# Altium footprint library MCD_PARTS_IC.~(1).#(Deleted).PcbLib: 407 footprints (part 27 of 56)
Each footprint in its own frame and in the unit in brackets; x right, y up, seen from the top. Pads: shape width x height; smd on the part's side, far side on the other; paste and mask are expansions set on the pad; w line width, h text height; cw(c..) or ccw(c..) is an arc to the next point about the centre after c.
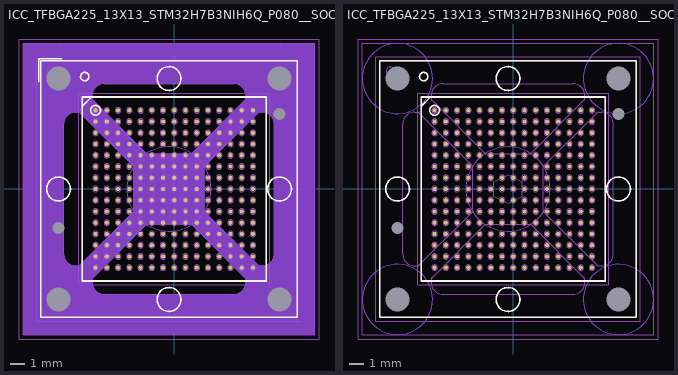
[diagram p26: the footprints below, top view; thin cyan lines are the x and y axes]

## ICC_TFBGA225_13X13_STM32H7B3NIH6Q_P080__SOCKET_IRONWOOD_CS1222291MF_REV-A [mm] "MCD-00670"
height 8.25
pads (231):
  round 0.3 smd mask+0.05: A1(-5.6,5.6) A2(-4.8,5.6) A3(-4,5.6) A4(-3.2,5.6) A5(-2.4,5.6) A6(-1.6,5.6) A7(-0.8,5.6) A8(0,5.6) A9(0.8,5.6) A10(1.6,5.6) A11(2.4,5.6) A12(3.2,5.6) A13(4,5.6) A14(4.8,5.6) A15(5.6,5.6) B1(-5.6,4.8) B2(-4.8,4.8) B3(-4,4.8) B4(-3.2,4.8) B5(-2.4,4.8) B6(-1.6,4.8) B7(-0.8,4.8) B8(0,4.8) B9(0.8,4.8) B10(1.6,4.8) B11(2.4,4.8) B12(3.2,4.8) B13(4,4.8) B14(4.8,4.8) B15(5.6,4.8) C1(-5.6,4) C2(-4.8,4) C3(-4,4) C4(-3.2,4) C5(-2.4,4) C6(-1.6,4) C7(-0.8,4) C8(0,4) C9(0.8,4) C10(1.6,4) C11(2.4,4) C12(3.2,4) C13(4,4) C14(4.8,4) C15(5.6,4) D1(-5.6,3.2) D2(-4.8,3.2) D3(-4,3.2) D4(-3.2,3.2) D5(-2.4,3.2) D6(-1.6,3.2) D7(-0.8,3.2) D8(0,3.2) D9(0.8,3.2) D10(1.6,3.2) D11(2.4,3.2) D12(3.2,3.2) D13(4,3.2) D14(4.8,3.2) D15(5.6,3.2) E1(-5.6,2.4) E2(-4.8,2.4) E3(-4,2.4) E4(-3.2,2.4) E5(-2.4,2.4) E6(-1.6,2.4) E7(-0.8,2.4) E8(0,2.4) E9(0.8,2.4) E10(1.6,2.4) E11(2.4,2.4) E12(3.2,2.4) E13(4,2.4) E14(4.8,2.4) E15(5.6,2.4) F1(-5.6,1.6) F2(-4.8,1.6) F3(-4,1.6) F4(-3.2,1.6) F5(-2.4,1.6) F6(-1.6,1.6) F7(-0.8,1.6) F8(0,1.6) F9(0.8,1.6) F10(1.6,1.6) F11(2.4,1.6) F12(3.2,1.6) F13(4,1.6) F14(4.8,1.6) F15(5.6,1.6) G1(-5.6,0.8) G2(-4.8,0.8) G3(-4,0.8) G4(-3.2,0.8) G5(-2.4,0.8) G6(-1.6,0.8) G7(-0.8,0.8) G8(0,0.8) G9(0.8,0.8) G10(1.6,0.8) G11(2.4,0.8) G12(3.2,0.8) G13(4,0.8) G14(4.8,0.8) G15(5.6,0.8) H1(-5.6,0) H2(-4.8,0) H3(-4,0) H4(-3.2,0) H5(-2.4,0) H6(-1.6,0) H7(-0.8,0) H8(0,0) H9(0.8,0) H10(1.6,0) H11(2.4,0) H12(3.2,0) H13(4,0) H14(4.8,0) H15(5.6,0) J1(-5.6,-0.8) J2(-4.8,-0.8) J3(-4,-0.8) J4(-3.2,-0.8) J5(-2.4,-0.8) J6(-1.6,-0.8) J7(-0.8,-0.8) J8(0,-0.8) J9(0.8,-0.8) J10(1.6,-0.8) J11(2.4,-0.8) J12(3.2,-0.8) J13(4,-0.8) J14(4.8,-0.8) J15(5.6,-0.8) K1(-5.6,-1.6) K2(-4.8,-1.6) K3(-4,-1.6) K4(-3.2,-1.6) K5(-2.4,-1.6) K6(-1.6,-1.6) K7(-0.8,-1.6) K8(0,-1.6) K9(0.8,-1.6) K10(1.6,-1.6) K11(2.4,-1.6) K12(3.2,-1.6) K13(4,-1.6) K14(4.8,-1.6) K15(5.6,-1.6) L1(-5.6,-2.4) L2(-4.8,-2.4) L3(-4,-2.4) L4(-3.2,-2.4) L5(-2.4,-2.4) L6(-1.6,-2.4) L7(-0.8,-2.4) L8(0,-2.4) L9(0.8,-2.4) L10(1.6,-2.4) L11(2.4,-2.4) L12(3.2,-2.4) L13(4,-2.4) L14(4.8,-2.4) L15(5.6,-2.4) M1(-5.6,-3.2) M2(-4.8,-3.2) M3(-4,-3.2) M4(-3.2,-3.2) M5(-2.4,-3.2) M6(-1.6,-3.2) M7(-0.8,-3.2) M8(0,-3.2) M9(0.8,-3.2) M10(1.6,-3.2) M11(2.4,-3.2) M12(3.2,-3.2) M13(4,-3.2) M14(4.8,-3.2) M15(5.6,-3.2) N1(-5.6,-4) N2(-4.8,-4) N3(-4,-4) N4(-3.2,-4) N5(-2.4,-4) N6(-1.6,-4) N7(-0.8,-4) N8(0,-4) N9(0.8,-4) N10(1.6,-4) N11(2.4,-4) N12(3.2,-4) N13(4,-4) N14(4.8,-4) N15(5.6,-4) P1(-5.6,-4.8) P2(-4.8,-4.8) P3(-4,-4.8) P4(-3.2,-4.8) P5(-2.4,-4.8) P6(-1.6,-4.8) P7(-0.8,-4.8) P8(0,-4.8) P9(0.8,-4.8) P10(1.6,-4.8) P11(2.4,-4.8) P12(3.2,-4.8) P13(4,-4.8) P14(4.8,-4.8) P15(5.6,-4.8) R1(-5.6,-5.6) R2(-4.8,-5.6) R3(-4,-5.6) R4(-3.2,-5.6) R5(-2.4,-5.6) R6(-1.6,-5.6) R7(-0.8,-5.6) R8(0,-5.6) R9(0.8,-5.6) R10(1.6,-5.6) R11(2.4,-5.6) R12(3.2,-5.6) R13(4,-5.6) R14(4.8,-5.6) R15(5.6,-5.6)
  round 0 hole 0.85 unplated mask+0.05: NPTH1(7.487,5.322) NPTH2(-8.238,-2.783)
  round 0 hole 1.71 unplated mask+0.05: PTH1(-8.238,7.862) PTH2(7.487,7.862) PTH3(7.487,-7.863) PTH4(-8.238,-7.863)
Bottom Layer keep-out:
  circle w0.01: c7.487,-7.863 r2.5
  circle w0.01: c-8.238,-7.863 r2.5
  circle w0.01: c-8.238,7.862 r2.5
  circle w0.01: c7.487,7.862 r2.5
  region: -0.376,0 -0.376,2.5 -1.976,2.5 -5.776,6.3 -5.792,6.317 -5.818,6.356 -5.836,6.4 -5.845,6.446 -5.846,6.469 -5.846,6.63 -5.842,6.715 -5.809,6.883 -5.743,7.04 -5.649,7.182 -5.528,7.303 -5.386,7.397 -5.229,7.463 -5.061,7.496 -4.976,7.5 -0.376,7.5 -0.376,10.365 -10.74,10.365 -10.74,-10.365 -0.376,-10.365 -0.376,-7.5 -4.976,-7.5 -5.061,-7.496 -5.229,-7.463 -5.386,-7.397 -5.528,-7.303 -5.649,-7.182 -5.743,-7.04 -5.809,-6.883 -5.842,-6.715 -5.846,-6.63 -5.846,-6.469 -5.845,-6.446 -5.836,-6.4 -5.818,-6.356 -5.792,-6.317 -5.776,-6.3 -1.976,-2.5 -0.376,-2.5 -0.376,0 -2.876,0 -2.876,-1.6 -6.676,-5.4 -6.693,-5.416 -6.732,-5.442 -6.776,-5.46 -6.822,-5.469 -6.845,-5.47 -7.006,-5.47 -7.091,-5.466 -7.259,-5.433 -7.416,-5.367 -7.558,-5.273 -7.679,-5.152 -7.773,-5.01 -7.839,-4.853 -7.872,-4.685 -7.876,-4.6 -7.876,4.6 -7.872,4.685 -7.839,4.853 -7.773,5.01 -7.679,5.152 -7.558,5.273 -7.416,5.367 -7.259,5.433 -7.091,5.466 -7.006,5.47 -6.845,5.47 -6.822,5.469 -6.776,5.46 -6.732,5.442 -6.693,5.416 -6.676,5.4 -2.876,1.6 -2.876,0
  region: -0.376,0 -0.376,-2.5 1.224,-2.5 5.024,-6.3 5.04,-6.317 5.066,-6.356 5.084,-6.4 5.093,-6.446 5.094,-6.469 5.094,-6.63 5.09,-6.715 5.057,-6.883 4.991,-7.04 4.897,-7.182 4.776,-7.303 4.634,-7.397 4.477,-7.463 4.309,-7.496 4.224,-7.5 -0.376,-7.5 -0.376,-10.365 9.988,-10.365 9.988,10.365 -0.376,10.365 -0.376,7.5 4.224,7.5 4.309,7.496 4.477,7.463 4.634,7.397 4.776,7.303 4.897,7.182 4.991,7.04 5.057,6.883 5.09,6.715 5.094,6.63 5.094,6.469 5.093,6.446 5.084,6.4 5.066,6.356 5.04,6.317 5.024,6.3 1.224,2.5 -0.376,2.5 -0.376,0 2.124,0 2.124,1.6 5.924,5.4 5.941,5.416 5.98,5.442 6.024,5.46 6.07,5.469 6.093,5.47 6.254,5.47 6.339,5.466 6.507,5.433 6.664,5.367 6.806,5.273 6.927,5.152 7.021,5.01 7.087,4.853 7.12,4.685 7.124,4.6 7.124,-4.6 7.12,-4.685 7.087,-4.853 7.021,-5.01 6.927,-5.152 6.806,-5.273 6.664,-5.367 6.507,-5.433 6.339,-5.466 6.254,-5.47 6.093,-5.47 6.07,-5.469 6.024,-5.46 5.98,-5.442 5.941,-5.416 5.924,-5.4 2.124,-1.6 2.124,0
Top Overlay:
  circle w0.12: c-5.6,5.6 r0.35
  circle w0.12: c-8.238,0 r0.85
  circle w0.12: c-0.375,7.862 r0.85
  circle w0.12: c7.487,0 r0.85
  circle w0.12: c-0.375,-7.863 r0.85
  circle w0.12: c-6.375,8 r0.3
  lines w0.12: -9.65,7.625 -9.65,9.275 -8,9.275 ; -6.55,5.895 -5.895,6.55 ; -9.5,-9.125 -9.5,9.125 8.75,9.125 8.75,-9.125 -9.5,-9.125 ; -6.55,-6.55 6.55,-6.55 6.55,6.55 -6.55,6.55 -6.55,-6.55
Bottom Overlay:
  lines w0.12: -10.75,-10.375 -10.75,10.375 -7.625,10.375 10,10.375 10,-10.375 -10.75,-10.375
M14-Top Assembly:
  drawing of 245 lines, arcs and shapes, not listed
  text "'.Designator'" at -6.5,7.25 h0.75
  text "A1" at -5.85,5.425 h0.4
M15-Bottom Assembly:
  lines w0.01: -2.891,1.615 -2.891,1.615 ; -2.891,1.615 -6.676,5.4 ccw(c-6.845,5.231) -6.845,5.47 -7.006,5.47 ccw(c-7.006,4.6) -7.876,4.6 -7.876,-4.6 ccw(c-7.006,-4.6) -7.006,-5.47 -6.845,-5.47 ccw(c-6.845,-5.231) -6.676,-5.4 -2.891,-1.615 -2.876,-1.6 -2.876,1.6 ; -2.891,1.615 -2.876,1.6 ; -2.876,1.6 -2.876,1.6 ; -1.991,-2.515 -1.976,-2.5 ; -1.991,-2.515 -5.776,-6.3 ccw(c-5.607,-6.469) -5.846,-6.469 -5.846,-6.63 ccw(c-4.976,-6.63) -4.976,-7.5 4.224,-7.5 ccw(c4.224,-6.63) 5.094,-6.63 5.094,-6.469 ccw(c4.855,-6.469) 5.024,-6.3 1.239,-2.515 1.224,-2.5 -1.976,-2.5 ; -1.991,-2.515 -1.991,-2.515 ; -1.976,-2.5 -1.976,-2.5 ; 1.224,2.5 -1.976,2.5 -1.991,2.515 -5.776,6.3 cw(c-5.607,6.469) -5.846,6.469 -5.846,6.63 cw(c-4.976,6.63) -4.976,7.5 4.224,7.5 cw(c4.224,6.63) 5.094,6.63 5.094,6.469 cw(c4.855,6.469) 5.024,6.3 1.239,2.515 ; 1.224,2.5 1.224,2.5 ; 1.224,2.5 1.239,2.515 ; 1.239,2.515 1.239,2.515 ; 2.124,-1.6 2.124,1.6 2.139,1.615 5.924,5.4 cw(c6.093,5.231) 6.093,5.47 6.254,5.47 cw(c6.254,4.6) 7.124,4.6 7.124,-4.6 cw(c6.254,-4.6) 6.254,-5.47 6.093,-5.47 cw(c6.093,-5.231) 5.924,-5.4 2.139,-1.615 ; 2.124,-1.6 2.124,-1.6 ; 2.124,-1.6 2.139,-1.615 ; 2.139,-1.615 2.139,-1.615 ; -10.74,-10.365 9.99,-10.365 9.99,10.365 -10.74,10.365 -10.74,-10.365
M16-Top Courtyard:
  lines w0.01: -9.8,-9.425 9.05,-9.425 9.05,9.425 -9.8,9.425 -9.8,8.5 -9.8,-9.425 ; -6.8,-6.8 -6.8,6.8 6.8,6.8 6.8,-6.8 -6.8,-6.8
M17-Bottom Courtyard:
  lines w0.01: -11.05,-10.675 -11.05,10.675 10.3,10.675 10.3,-10.675 -11.05,-10.675
3D body: height 1.21, standoff 1.2, extent -5.898,5.301 -5.3,5.9
3D body: height 0.36, standoff -0.04, extent 5.401,-5.797 5.8,-5.403
3D body: height 0.36, standoff -0.04, extent 4.601,-5.797 5,-5.403
3D body: height 0.36, standoff -0.04, extent 3.801,-5.797 4.2,-5.403
3D body: height 0.36, standoff -0.04, extent 3.001,-5.797 3.4,-5.403
3D body: height 0.36, standoff -0.04, extent 2.201,-5.797 2.6,-5.403
3D body: height 0.36, standoff -0.04, extent -1.799,-5.797 -1.4,-5.403
3D body: height 0.36, standoff -0.04, extent -0.999,-5.797 -0.6,-5.403
3D body: height 0.36, standoff -0.04, extent -0.199,-5.797 0.2,-5.403
3D body: height 0.36, standoff -0.04, extent 0.601,-5.797 1,-5.403
3D body: height 0.36, standoff -0.04, extent 1.401,-5.797 1.8,-5.403
3D body: height 0.36, standoff -0.04, extent -5.799,-5.797 -5.4,-5.403
3D body: height 0.36, standoff -0.04, extent -4.999,-5.797 -4.6,-5.403
3D body: height 0.36, standoff -0.04, extent -4.199,-5.797 -3.8,-5.403
3D body: height 0.36, standoff -0.04, extent -3.399,-5.797 -3,-5.403
3D body: height 0.36, standoff -0.04, extent -2.599,-5.797 -2.2,-5.403
3D body: height 0.36, standoff -0.04, extent 5.401,-4.997 5.8,-4.603
3D body: height 0.36, standoff -0.04, extent 4.601,-4.997 5,-4.603
3D body: height 0.36, standoff -0.04, extent 3.801,-4.997 4.2,-4.603
3D body: height 0.36, standoff -0.04, extent 3.001,-4.997 3.4,-4.603
3D body: height 0.36, standoff -0.04, extent 2.201,-4.997 2.6,-4.603
3D body: height 0.36, standoff -0.04, extent -1.799,-4.997 -1.4,-4.603
3D body: height 0.36, standoff -0.04, extent -0.999,-4.997 -0.6,-4.603
3D body: height 0.36, standoff -0.04, extent -0.199,-4.997 0.2,-4.603
3D body: height 0.36, standoff -0.04, extent 0.601,-4.997 1,-4.603
3D body: height 0.36, standoff -0.04, extent 1.401,-4.997 1.8,-4.603
3D body: height 0.36, standoff -0.04, extent -5.799,-4.997 -5.4,-4.603
3D body: height 0.36, standoff -0.04, extent -4.999,-4.997 -4.6,-4.603
3D body: height 0.36, standoff -0.04, extent -4.199,-4.997 -3.8,-4.603
3D body: height 0.36, standoff -0.04, extent -3.399,-4.997 -3,-4.603
3D body: height 0.36, standoff -0.04, extent -2.599,-4.997 -2.2,-4.603
3D body: height 0.36, standoff -0.04, extent 5.401,-4.197 5.8,-3.803
3D body: height 0.36, standoff -0.04, extent 4.601,-4.197 5,-3.803
3D body: height 0.36, standoff -0.04, extent 3.801,-4.197 4.2,-3.803
3D body: height 0.36, standoff -0.04, extent 3.001,-4.197 3.4,-3.803
3D body: height 0.36, standoff -0.04, extent 2.201,-4.197 2.6,-3.803
3D body: height 0.36, standoff -0.04, extent -1.799,-4.197 -1.4,-3.803
3D body: height 0.36, standoff -0.04, extent -0.999,-4.197 -0.6,-3.803
3D body: height 0.36, standoff -0.04, extent -0.199,-4.197 0.2,-3.803
3D body: height 0.36, standoff -0.04, extent 0.601,-4.197 1,-3.803
3D body: height 0.36, standoff -0.04, extent 1.401,-4.197 1.8,-3.803
3D body: height 0.36, standoff -0.04, extent -5.799,-4.197 -5.4,-3.803
3D body: height 0.36, standoff -0.04, extent -4.999,-4.197 -4.6,-3.803
3D body: height 0.36, standoff -0.04, extent -4.199,-4.197 -3.8,-3.803
3D body: height 0.36, standoff -0.04, extent -3.399,-4.197 -3,-3.803
3D body: height 0.36, standoff -0.04, extent -2.599,-4.197 -2.2,-3.803
3D body: height 0.36, standoff -0.04, extent 5.401,-3.397 5.8,-3.003
3D body: height 0.36, standoff -0.04, extent 4.601,-3.397 5,-3.003
3D body: height 0.36, standoff -0.04, extent 3.801,-3.397 4.2,-3.003
3D body: height 0.36, standoff -0.04, extent 3.001,-3.397 3.4,-3.003
3D body: height 0.36, standoff -0.04, extent 2.201,-3.397 2.6,-3.003
3D body: height 0.36, standoff -0.04, extent -1.799,-3.397 -1.4,-3.003
3D body: height 0.36, standoff -0.04, extent -0.999,-3.397 -0.6,-3.003
3D body: height 0.36, standoff -0.04, extent -0.199,-3.397 0.2,-3.003
3D body: height 0.36, standoff -0.04, extent 0.601,-3.397 1,-3.003
3D body: height 0.36, standoff -0.04, extent 1.401,-3.397 1.8,-3.003
3D body: height 0.36, standoff -0.04, extent -5.799,-3.397 -5.4,-3.003
3D body: height 0.36, standoff -0.04, extent -4.999,-3.397 -4.6,-3.003
3D body: height 0.36, standoff -0.04, extent -4.199,-3.397 -3.8,-3.003
3D body: height 0.36, standoff -0.04, extent -3.399,-3.397 -3,-3.003
3D body: height 0.36, standoff -0.04, extent -2.599,-3.397 -2.2,-3.003
3D body: height 0.36, standoff -0.04, extent 5.401,-2.597 5.8,-2.203
3D body: height 0.36, standoff -0.04, extent 4.601,-2.597 5,-2.203
3D body: height 0.36, standoff -0.04, extent 3.801,-2.597 4.2,-2.203
3D body: height 0.36, standoff -0.04, extent 3.001,-2.597 3.4,-2.203
3D body: height 0.36, standoff -0.04, extent 2.201,-2.597 2.6,-2.203
3D body: height 0.36, standoff -0.04, extent -1.799,-2.597 -1.4,-2.203
3D body: height 0.36, standoff -0.04, extent -0.999,-2.597 -0.6,-2.203
3D body: height 0.36, standoff -0.04, extent -0.199,-2.597 0.2,-2.203
3D body: height 0.36, standoff -0.04, extent 0.601,-2.597 1,-2.203
3D body: height 0.36, standoff -0.04, extent 1.401,-2.597 1.8,-2.203
3D body: height 0.36, standoff -0.04, extent -5.799,-2.597 -5.4,-2.203
3D body: height 0.36, standoff -0.04, extent -4.999,-2.597 -4.6,-2.203
3D body: height 0.36, standoff -0.04, extent -4.199,-2.597 -3.8,-2.203
3D body: height 0.36, standoff -0.04, extent -3.399,-2.597 -3,-2.203
3D body: height 0.36, standoff -0.04, extent -2.599,-2.597 -2.2,-2.203
3D body: height 0.36, standoff -0.04, extent 5.401,-1.797 5.8,-1.403
3D body: height 0.36, standoff -0.04, extent 4.601,-1.797 5,-1.403
3D body: height 0.36, standoff -0.04, extent 3.801,-1.797 4.2,-1.403
3D body: height 0.36, standoff -0.04, extent 3.001,-1.797 3.4,-1.403
3D body: height 0.36, standoff -0.04, extent 2.201,-1.797 2.6,-1.403
3D body: height 0.36, standoff -0.04, extent -1.799,-1.797 -1.4,-1.403
3D body: height 0.36, standoff -0.04, extent -0.999,-1.797 -0.6,-1.403
3D body: height 0.36, standoff -0.04, extent -0.199,-1.797 0.2,-1.403
3D body: height 0.36, standoff -0.04, extent 0.601,-1.797 1,-1.403
3D body: height 0.36, standoff -0.04, extent 1.401,-1.797 1.8,-1.403
3D body: height 0.36, standoff -0.04, extent -5.799,-1.797 -5.4,-1.403
3D body: height 0.36, standoff -0.04, extent -4.999,-1.797 -4.6,-1.403
3D body: height 0.36, standoff -0.04, extent -4.199,-1.797 -3.8,-1.403
3D body: height 0.36, standoff -0.04, extent -3.399,-1.797 -3,-1.403
3D body: height 0.36, standoff -0.04, extent -2.599,-1.797 -2.2,-1.403
3D body: height 0.36, standoff -0.04, extent 5.401,-0.997 5.8,-0.603
3D body: height 0.36, standoff -0.04, extent 4.601,-0.997 5,-0.603
3D body: height 0.36, standoff -0.04, extent 3.801,-0.997 4.2,-0.603
3D body: height 0.36, standoff -0.04, extent 3.001,-0.997 3.4,-0.603
3D body: height 0.36, standoff -0.04, extent 2.201,-0.997 2.6,-0.603
3D body: height 0.36, standoff -0.04, extent -1.799,-0.997 -1.4,-0.603
3D body: height 0.36, standoff -0.04, extent -0.999,-0.997 -0.6,-0.603
3D body: height 0.36, standoff -0.04, extent -0.199,-0.997 0.2,-0.603
3D body: height 0.36, standoff -0.04, extent 0.601,-0.997 1,-0.603
3D body: height 0.36, standoff -0.04, extent 1.401,-0.997 1.8,-0.603
3D body: height 0.36, standoff -0.04, extent -5.799,-0.997 -5.4,-0.603
3D body: height 0.36, standoff -0.04, extent -4.999,-0.997 -4.6,-0.603
3D body: height 0.36, standoff -0.04, extent -4.199,-0.997 -3.8,-0.603
3D body: height 0.36, standoff -0.04, extent -3.399,-0.997 -3,-0.603
3D body: height 0.36, standoff -0.04, extent -2.599,-0.997 -2.2,-0.603
3D body: height 0.36, standoff -0.04, extent 5.401,-0.197 5.8,0.197
3D body: height 0.36, standoff -0.04, extent 4.601,-0.197 5,0.197
3D body: height 0.36, standoff -0.04, extent 3.801,-0.197 4.2,0.197
3D body: height 0.36, standoff -0.04, extent 3.001,-0.197 3.4,0.197
3D body: height 0.36, standoff -0.04, extent 2.201,-0.197 2.6,0.197
3D body: height 0.36, standoff -0.04, extent -1.799,-0.197 -1.4,0.197
3D body: height 0.36, standoff -0.04, extent -0.999,-0.197 -0.6,0.197
3D body: height 0.36, standoff -0.04, extent -0.199,-0.197 0.2,0.197
3D body: height 0.36, standoff -0.04, extent 0.601,-0.197 1,0.197
3D body: height 0.36, standoff -0.04, extent 1.401,-0.197 1.8,0.197
3D body: height 0.36, standoff -0.04, extent -5.799,-0.197 -5.4,0.197
3D body: height 0.36, standoff -0.04, extent -4.999,-0.197 -4.6,0.197
3D body: height 0.36, standoff -0.04, extent -4.199,-0.197 -3.8,0.197
3D body: height 0.36, standoff -0.04, extent -3.399,-0.197 -3,0.197
3D body: height 0.36, standoff -0.04, extent -2.599,-0.197 -2.2,0.197
3D body: height 0.36, standoff -0.04, extent 5.401,0.603 5.8,0.997
3D body: height 0.36, standoff -0.04, extent 4.601,0.603 5,0.997
3D body: height 0.36, standoff -0.04, extent 3.801,0.603 4.2,0.997
3D body: height 0.36, standoff -0.04, extent 3.001,0.603 3.4,0.997
3D body: height 0.36, standoff -0.04, extent 2.201,0.603 2.6,0.997
3D body: height 0.36, standoff -0.04, extent -1.799,0.603 -1.4,0.997
3D body: height 0.36, standoff -0.04, extent -0.999,0.603 -0.6,0.997
3D body: height 0.36, standoff -0.04, extent -0.199,0.603 0.2,0.997
3D body: height 0.36, standoff -0.04, extent 0.601,0.603 1,0.997
3D body: height 0.36, standoff -0.04, extent 1.401,0.603 1.8,0.997
3D body: height 0.36, standoff -0.04, extent -5.799,0.603 -5.4,0.997
3D body: height 0.36, standoff -0.04, extent -4.999,0.603 -4.6,0.997
3D body: height 0.36, standoff -0.04, extent -4.199,0.603 -3.8,0.997
3D body: height 0.36, standoff -0.04, extent -3.399,0.603 -3,0.997
3D body: height 0.36, standoff -0.04, extent -2.599,0.603 -2.2,0.997
3D body: height 0.36, standoff -0.04, extent 5.401,1.403 5.8,1.797
3D body: height 0.36, standoff -0.04, extent 4.601,1.403 5,1.797
3D body: height 0.36, standoff -0.04, extent 3.801,1.403 4.2,1.797
3D body: height 0.36, standoff -0.04, extent 3.001,1.403 3.4,1.797
3D body: height 0.36, standoff -0.04, extent 2.201,1.403 2.6,1.797
3D body: height 0.36, standoff -0.04, extent -1.799,1.403 -1.4,1.797
3D body: height 0.36, standoff -0.04, extent -0.999,1.403 -0.6,1.797
3D body: height 0.36, standoff -0.04, extent -0.199,1.403 0.2,1.797
3D body: height 0.36, standoff -0.04, extent 0.601,1.403 1,1.797
3D body: height 0.36, standoff -0.04, extent 1.401,1.403 1.8,1.797
3D body: height 0.36, standoff -0.04, extent -5.799,1.403 -5.4,1.797
3D body: height 0.36, standoff -0.04, extent -4.999,1.403 -4.6,1.797
3D body: height 0.36, standoff -0.04, extent -4.199,1.403 -3.8,1.797
3D body: height 0.36, standoff -0.04, extent -3.399,1.403 -3,1.797
3D body: height 0.36, standoff -0.04, extent -2.599,1.403 -2.2,1.797
3D body: height 0.36, standoff -0.04, extent 5.401,2.203 5.8,2.597
3D body: height 0.36, standoff -0.04, extent 4.601,2.203 5,2.597
3D body: height 0.36, standoff -0.04, extent 3.801,2.203 4.2,2.597
3D body: height 0.36, standoff -0.04, extent 3.001,2.203 3.4,2.597
3D body: height 0.36, standoff -0.04, extent 2.201,2.203 2.6,2.597
3D body: height 0.36, standoff -0.04, extent -1.799,2.203 -1.4,2.597
3D body: height 0.36, standoff -0.04, extent -0.999,2.203 -0.6,2.597
3D body: height 0.36, standoff -0.04, extent -0.199,2.203 0.2,2.597
3D body: height 0.36, standoff -0.04, extent 0.601,2.203 1,2.597
3D body: height 0.36, standoff -0.04, extent 1.401,2.203 1.8,2.597
3D body: height 0.36, standoff -0.04, extent -5.799,2.203 -5.4,2.597
3D body: height 0.36, standoff -0.04, extent -4.999,2.203 -4.6,2.597
3D body: height 0.36, standoff -0.04, extent -4.199,2.203 -3.8,2.597
3D body: height 0.36, standoff -0.04, extent -3.399,2.203 -3,2.597
3D body: height 0.36, standoff -0.04, extent -2.599,2.203 -2.2,2.597
3D body: height 0.36, standoff -0.04, extent 5.401,3.003 5.8,3.397
3D body: height 0.36, standoff -0.04, extent 4.601,3.003 5,3.397
3D body: height 0.36, standoff -0.04, extent 3.801,3.003 4.2,3.397
3D body: height 0.36, standoff -0.04, extent 3.001,3.003 3.4,3.397
3D body: height 0.36, standoff -0.04, extent 2.201,3.003 2.6,3.397
3D body: height 0.36, standoff -0.04, extent -1.799,3.003 -1.4,3.397
3D body: height 0.36, standoff -0.04, extent -0.999,3.003 -0.6,3.397
3D body: height 0.36, standoff -0.04, extent -0.199,3.003 0.2,3.397
3D body: height 0.36, standoff -0.04, extent 0.601,3.003 1,3.397
3D body: height 0.36, standoff -0.04, extent 1.401,3.003 1.8,3.397
3D body: height 0.36, standoff -0.04, extent -5.799,3.003 -5.4,3.397
3D body: height 0.36, standoff -0.04, extent -4.999,3.003 -4.6,3.397
3D body: height 0.36, standoff -0.04, extent -4.199,3.003 -3.8,3.397
3D body: height 0.36, standoff -0.04, extent -3.399,3.003 -3,3.397
3D body: height 0.36, standoff -0.04, extent -2.599,3.003 -2.2,3.397
3D body: height 0.36, standoff -0.04, extent 5.401,3.803 5.8,4.197
3D body: height 0.36, standoff -0.04, extent 4.601,3.803 5,4.197
3D body: height 0.36, standoff -0.04, extent 3.801,3.803 4.2,4.197
3D body: height 0.36, standoff -0.04, extent 3.001,3.803 3.4,4.197
3D body: height 0.36, standoff -0.04, extent 2.201,3.803 2.6,4.197
3D body: height 0.36, standoff -0.04, extent -1.799,3.803 -1.4,4.197
3D body: height 0.36, standoff -0.04, extent -0.999,3.803 -0.6,4.197
3D body: height 0.36, standoff -0.04, extent -0.199,3.803 0.2,4.197
3D body: height 0.36, standoff -0.04, extent 0.601,3.803 1,4.197
3D body: height 0.36, standoff -0.04, extent 1.401,3.803 1.8,4.197
3D body: height 0.36, standoff -0.04, extent -5.799,3.803 -5.4,4.197
3D body: height 0.36, standoff -0.04, extent -4.999,3.803 -4.6,4.197
3D body: height 0.36, standoff -0.04, extent -4.199,3.803 -3.8,4.197
3D body: height 0.36, standoff -0.04, extent -3.399,3.803 -3,4.197
3D body: height 0.36, standoff -0.04, extent -2.599,3.803 -2.2,4.197
3D body: height 0.36, standoff -0.04, extent 5.401,4.603 5.8,4.997
3D body: height 0.36, standoff -0.04, extent 4.601,4.603 5,4.997
3D body: height 0.36, standoff -0.04, extent 3.801,4.603 4.2,4.997
3D body: height 0.36, standoff -0.04, extent 3.001,4.603 3.4,4.997
3D body: height 0.36, standoff -0.04, extent 2.201,4.603 2.6,4.997
3D body: height 0.36, standoff -0.04, extent -1.799,4.603 -1.4,4.997
3D body: height 0.36, standoff -0.04, extent -0.999,4.603 -0.6,4.997
3D body: height 0.36, standoff -0.04, extent -0.199,4.603 0.2,4.997
3D body: height 0.36, standoff -0.04, extent 0.601,4.603 1,4.997
3D body: height 0.36, standoff -0.04, extent 1.401,4.603 1.8,4.997
3D body: height 0.36, standoff -0.04, extent -5.799,4.603 -5.4,4.997
3D body: height 0.36, standoff -0.04, extent -4.999,4.603 -4.6,4.997
3D body: height 0.36, standoff -0.04, extent -4.199,4.603 -3.8,4.997
3D body: height 0.36, standoff -0.04, extent -3.399,4.603 -3,4.997
3D body: height 0.36, standoff -0.04, extent -2.599,4.603 -2.2,4.997
3D body: height 0.36, standoff -0.04, extent -2.599,5.403 -2.2,5.797
3D body: height 0.36, standoff -0.04, extent -3.399,5.403 -3,5.797
3D body: height 0.36, standoff -0.04, extent -4.199,5.403 -3.8,5.797
3D body: height 0.36, standoff -0.04, extent -4.999,5.403 -4.6,5.797
3D body: height 0.36, standoff -0.04, extent -5.799,5.403 -5.4,5.797
3D body: height 0.36, standoff -0.04, extent 1.401,5.403 1.8,5.797
3D body: height 0.36, standoff -0.04, extent 0.601,5.403 1,5.797
3D body: height 0.36, standoff -0.04, extent -0.199,5.403 0.2,5.797
3D body: height 0.36, standoff -0.04, extent -0.999,5.403 -0.6,5.797
3D body: height 0.36, standoff -0.04, extent -1.799,5.403 -1.4,5.797
3D body: height 0.36, standoff -0.04, extent 2.201,5.403 2.6,5.797
3D body: height 0.36, standoff -0.04, extent 3.001,5.403 3.4,5.797
3D body: height 0.36, standoff -0.04, extent 3.801,5.403 4.2,5.797
3D body: height 0.36, standoff -0.04, extent 4.601,5.403 5,5.797
3D body: height 1.2, standoff 0.3, extent -6.55,-6.55 6.55,6.55
3D body: height 0.36, standoff -0.04, extent 5.401,5.403 5.8,5.797
3D body: height 8.26, standoff 8.25, extent -1.375,-1 0.625,1
3D body: height 5, standoff 0, extent -9.488,-9.113 8.737,9.112
3D body: height 8.25, standoff 5, extent -3.375,-3 2.625,3
3D body: height 6, standoff 5, extent -1.218,-8.711 0.475,-7.014
3D body: height 6, standoff 5, extent 6.644,-0.848 8.338,0.848
3D body: height 6, standoff 5, extent -1.218,7.014 0.475,8.711
3D body: height 6, standoff 5, extent -9.081,-0.848 -7.387,0.848
3D body: height -1.6, standoff -3.2, extent -10.74,-10.365 9.99,10.365
3D body: height -3.2, standoff -9.55, extent -10.74,-10.365 9.99,10.365

## ICC_TFBGA225_13X13_STM32H7B3NIH6Q_P080__SOCKET_IRONWOOD_CS1222291MF_REV-A_17.0 [mm]
height 8.25
pads (231):
  round 0.3 smd mask+0.05: A1(-5.6,5.6) A2(-4.8,5.6) A3(-4,5.6) A4(-3.2,5.6) A5(-2.4,5.6) A6(-1.6,5.6) A7(-0.8,5.6) A8(0,5.6) A9(0.8,5.6) A10(1.6,5.6) A11(2.4,5.6) A12(3.2,5.6) A13(4,5.6) A14(4.8,5.6) A15(5.6,5.6) B1(-5.6,4.8) B2(-4.8,4.8) B3(-4,4.8) B4(-3.2,4.8) B5(-2.4,4.8) B6(-1.6,4.8) B7(-0.8,4.8) B8(0,4.8) B9(0.8,4.8) B10(1.6,4.8) B11(2.4,4.8) B12(3.2,4.8) B13(4,4.8) B14(4.8,4.8) B15(5.6,4.8) C1(-5.6,4) C2(-4.8,4) C3(-4,4) C4(-3.2,4) C5(-2.4,4) C6(-1.6,4) C7(-0.8,4) C8(0,4) C9(0.8,4) C10(1.6,4) C11(2.4,4) C12(3.2,4) C13(4,4) C14(4.8,4) C15(5.6,4) D1(-5.6,3.2) D2(-4.8,3.2) D3(-4,3.2) D4(-3.2,3.2) D5(-2.4,3.2) D6(-1.6,3.2) D7(-0.8,3.2) D8(0,3.2) D9(0.8,3.2) D10(1.6,3.2) D11(2.4,3.2) D12(3.2,3.2) D13(4,3.2) D14(4.8,3.2) D15(5.6,3.2) E1(-5.6,2.4) E2(-4.8,2.4) E3(-4,2.4) E4(-3.2,2.4) E5(-2.4,2.4) E6(-1.6,2.4) E7(-0.8,2.4) E8(0,2.4) E9(0.8,2.4) E10(1.6,2.4) E11(2.4,2.4) E12(3.2,2.4) E13(4,2.4) E14(4.8,2.4) E15(5.6,2.4) F1(-5.6,1.6) F2(-4.8,1.6) F3(-4,1.6) F4(-3.2,1.6) F5(-2.4,1.6) F6(-1.6,1.6) F7(-0.8,1.6) F8(0,1.6) F9(0.8,1.6) F10(1.6,1.6) F11(2.4,1.6) F12(3.2,1.6) F13(4,1.6) F14(4.8,1.6) F15(5.6,1.6) G1(-5.6,0.8) G2(-4.8,0.8) G3(-4,0.8) G4(-3.2,0.8) G5(-2.4,0.8) G6(-1.6,0.8) G7(-0.8,0.8) G8(0,0.8) G9(0.8,0.8) G10(1.6,0.8) G11(2.4,0.8) G12(3.2,0.8) G13(4,0.8) G14(4.8,0.8) G15(5.6,0.8) H1(-5.6,0) H2(-4.8,0) H3(-4,0) H4(-3.2,0) H5(-2.4,0) H6(-1.6,0) H7(-0.8,0) H8(0,0) H9(0.8,0) H10(1.6,0) H11(2.4,0) H12(3.2,0) H13(4,0) H14(4.8,0) H15(5.6,0) J1(-5.6,-0.8) J2(-4.8,-0.8) J3(-4,-0.8) J4(-3.2,-0.8) J5(-2.4,-0.8) J6(-1.6,-0.8) J7(-0.8,-0.8) J8(0,-0.8) J9(0.8,-0.8) J10(1.6,-0.8) J11(2.4,-0.8) J12(3.2,-0.8) J13(4,-0.8) J14(4.8,-0.8) J15(5.6,-0.8) K1(-5.6,-1.6) K2(-4.8,-1.6) K3(-4,-1.6) K4(-3.2,-1.6) K5(-2.4,-1.6) K6(-1.6,-1.6) K7(-0.8,-1.6) K8(0,-1.6) K9(0.8,-1.6) K10(1.6,-1.6) K11(2.4,-1.6) K12(3.2,-1.6) K13(4,-1.6) K14(4.8,-1.6) K15(5.6,-1.6) L1(-5.6,-2.4) L2(-4.8,-2.4) L3(-4,-2.4) L4(-3.2,-2.4) L5(-2.4,-2.4) L6(-1.6,-2.4) L7(-0.8,-2.4) L8(0,-2.4) L9(0.8,-2.4) L10(1.6,-2.4) L11(2.4,-2.4) L12(3.2,-2.4) L13(4,-2.4) L14(4.8,-2.4) L15(5.6,-2.4) M1(-5.6,-3.2) M2(-4.8,-3.2) M3(-4,-3.2) M4(-3.2,-3.2) M5(-2.4,-3.2) M6(-1.6,-3.2) M7(-0.8,-3.2) M8(0,-3.2) M9(0.8,-3.2) M10(1.6,-3.2) M11(2.4,-3.2) M12(3.2,-3.2) M13(4,-3.2) M14(4.8,-3.2) M15(5.6,-3.2) N1(-5.6,-4) N2(-4.8,-4) N3(-4,-4) N4(-3.2,-4) N5(-2.4,-4) N6(-1.6,-4) N7(-0.8,-4) N8(0,-4) N9(0.8,-4) N10(1.6,-4) N11(2.4,-4) N12(3.2,-4) N13(4,-4) N14(4.8,-4) N15(5.6,-4) P1(-5.6,-4.8) P2(-4.8,-4.8) P3(-4,-4.8) P4(-3.2,-4.8) P5(-2.4,-4.8) P6(-1.6,-4.8) P7(-0.8,-4.8) P8(0,-4.8) P9(0.8,-4.8) P10(1.6,-4.8) P11(2.4,-4.8) P12(3.2,-4.8) P13(4,-4.8) P14(4.8,-4.8) P15(5.6,-4.8) R1(-5.6,-5.6) R2(-4.8,-5.6) R3(-4,-5.6) R4(-3.2,-5.6) R5(-2.4,-5.6) R6(-1.6,-5.6) R7(-0.8,-5.6) R8(0,-5.6) R9(0.8,-5.6) R10(1.6,-5.6) R11(2.4,-5.6) R12(3.2,-5.6) R13(4,-5.6) R14(4.8,-5.6) R15(5.6,-5.6)
  round 0 hole 0.85 unplated mask+0.05: NPTH1(7.487,5.322) NPTH2(-8.238,-2.783)
  round 0 hole 1.71 unplated mask+0.05: PTH1(-8.238,7.862) PTH2(7.487,7.862) PTH3(7.487,-7.863) PTH4(-8.238,-7.863)
Bottom Layer keep-out:
  circle w0.01: c7.487,-7.863 r2.5
  circle w0.01: c-8.238,-7.863 r2.5
  circle w0.01: c-8.238,7.862 r2.5
  circle w0.01: c7.487,7.862 r2.5
Top Overlay:
  circle w0.12: c-5.6,5.6 r0.35
  circle w0.12: c-8.238,0 r0.85
  circle w0.12: c-0.375,7.862 r0.85
  circle w0.12: c7.487,0 r0.85
  circle w0.12: c-0.375,-7.863 r0.85
  circle w0.12: c-6.375,8 r0.3
  lines w0.12: -6.55,5.895 -5.895,6.55 ; -9.5,-9.125 -9.5,9.125 8.75,9.125 8.75,-9.125 -9.5,-9.125 ; -6.55,-6.55 6.55,-6.55 6.55,6.55 -6.55,6.55 -6.55,-6.55
Bottom Overlay:
  lines w0.12: -10.75,-10.375 -10.75,10.375 -7.625,10.375 10,10.375 10,-10.375 -10.75,-10.375
M14-Top Assembly:
  drawing of 245 lines, arcs and shapes, not listed
  text "'.Designator'" at -6.5,7.5 h0.75
  text "A1" at -5.85,5.425 h0.4
M15-Bottom Assembly:
  lines w0.01: -2.891,1.615 -2.891,1.615 ; -2.891,1.615 -6.676,5.4 ccw(c-6.845,5.231) -6.845,5.47 -7.006,5.47 ccw(c-7.006,4.6) -7.876,4.6 -7.876,-4.6 ccw(c-7.006,-4.6) -7.006,-5.47 -6.845,-5.47 ccw(c-6.845,-5.231) -6.676,-5.4 -2.891,-1.615 -2.876,-1.6 -2.876,1.6 ; -2.891,1.615 -2.876,1.6 ; -2.876,1.6 -2.876,1.6 ; -1.991,-2.515 -1.976,-2.5 ; -1.991,-2.515 -5.776,-6.3 ccw(c-5.607,-6.469) -5.846,-6.469 -5.846,-6.63 ccw(c-4.976,-6.63) -4.976,-7.5 4.224,-7.5 ccw(c4.224,-6.63) 5.094,-6.63 5.094,-6.469 ccw(c4.855,-6.469) 5.024,-6.3 1.239,-2.515 1.224,-2.5 -1.976,-2.5 ; -1.991,-2.515 -1.991,-2.515 ; -1.976,-2.5 -1.976,-2.5 ; 1.224,2.5 -1.976,2.5 -1.991,2.515 -5.776,6.3 cw(c-5.607,6.469) -5.846,6.469 -5.846,6.63 cw(c-4.976,6.63) -4.976,7.5 4.224,7.5 cw(c4.224,6.63) 5.094,6.63 5.094,6.469 cw(c4.855,6.469) 5.024,6.3 1.239,2.515 ; 1.224,2.5 1.224,2.5 ; 1.224,2.5 1.239,2.515 ; 1.239,2.515 1.239,2.515 ; 2.124,-1.6 2.124,1.6 2.139,1.615 5.924,5.4 cw(c6.093,5.231) 6.093,5.47 6.254,5.47 cw(c6.254,4.6) 7.124,4.6 7.124,-4.6 cw(c6.254,-4.6) 6.254,-5.47 6.093,-5.47 cw(c6.093,-5.231) 5.924,-5.4 2.139,-1.615 ; 2.124,-1.6 2.124,-1.6 ; 2.124,-1.6 2.139,-1.615 ; 2.139,-1.615 2.139,-1.615 ; -10.74,-10.365 9.99,-10.365 9.99,10.365 -10.74,10.365 -10.74,-10.365
M16-Top Courtyard:
  lines w0.01: -9.8,-9.425 9.05,-9.425 9.05,9.425 -9.8,9.425 -9.8,8.5 -9.8,-9.425 ; -6.8,-6.8 -6.8,6.8 6.8,6.8 6.8,-6.8 -6.8,-6.8
M17-Bottom Courtyard:
  lines w0.01: -11.05,-10.675 -11.05,10.675 10.3,10.675 10.3,-10.675 -11.05,-10.675
3D body: height 1.21, standoff 1.2, extent -5.898,5.301 -5.3,5.9
3D body: height 0.36, standoff -0.04, extent 5.401,-5.797 5.8,-5.403
3D body: height 0.36, standoff -0.04, extent 4.601,-5.797 5,-5.403
3D body: height 0.36, standoff -0.04, extent 3.801,-5.797 4.2,-5.403
3D body: height 0.36, standoff -0.04, extent 3.001,-5.797 3.4,-5.403
3D body: height 0.36, standoff -0.04, extent 2.201,-5.797 2.6,-5.403
3D body: height 0.36, standoff -0.04, extent -1.799,-5.797 -1.4,-5.403
3D body: height 0.36, standoff -0.04, extent -0.999,-5.797 -0.6,-5.403
3D body: height 0.36, standoff -0.04, extent -0.199,-5.797 0.2,-5.403
3D body: height 0.36, standoff -0.04, extent 0.601,-5.797 1,-5.403
3D body: height 0.36, standoff -0.04, extent 1.401,-5.797 1.8,-5.403
3D body: height 0.36, standoff -0.04, extent -5.799,-5.797 -5.4,-5.403
3D body: height 0.36, standoff -0.04, extent -4.999,-5.797 -4.6,-5.403
3D body: height 0.36, standoff -0.04, extent -4.199,-5.797 -3.8,-5.403
3D body: height 0.36, standoff -0.04, extent -3.399,-5.797 -3,-5.403
3D body: height 0.36, standoff -0.04, extent -2.599,-5.797 -2.2,-5.403
3D body: height 0.36, standoff -0.04, extent 5.401,-4.997 5.8,-4.603
3D body: height 0.36, standoff -0.04, extent 4.601,-4.997 5,-4.603
3D body: height 0.36, standoff -0.04, extent 3.801,-4.997 4.2,-4.603
3D body: height 0.36, standoff -0.04, extent 3.001,-4.997 3.4,-4.603
3D body: height 0.36, standoff -0.04, extent 2.201,-4.997 2.6,-4.603
3D body: height 0.36, standoff -0.04, extent -1.799,-4.997 -1.4,-4.603
3D body: height 0.36, standoff -0.04, extent -0.999,-4.997 -0.6,-4.603
3D body: height 0.36, standoff -0.04, extent -0.199,-4.997 0.2,-4.603
3D body: height 0.36, standoff -0.04, extent 0.601,-4.997 1,-4.603
3D body: height 0.36, standoff -0.04, extent 1.401,-4.997 1.8,-4.603
3D body: height 0.36, standoff -0.04, extent -5.799,-4.997 -5.4,-4.603
3D body: height 0.36, standoff -0.04, extent -4.999,-4.997 -4.6,-4.603
3D body: height 0.36, standoff -0.04, extent -4.199,-4.997 -3.8,-4.603
3D body: height 0.36, standoff -0.04, extent -3.399,-4.997 -3,-4.603
3D body: height 0.36, standoff -0.04, extent -2.599,-4.997 -2.2,-4.603
3D body: height 0.36, standoff -0.04, extent 5.401,-4.197 5.8,-3.803
3D body: height 0.36, standoff -0.04, extent 4.601,-4.197 5,-3.803
3D body: height 0.36, standoff -0.04, extent 3.801,-4.197 4.2,-3.803
3D body: height 0.36, standoff -0.04, extent 3.001,-4.197 3.4,-3.803
3D body: height 0.36, standoff -0.04, extent 2.201,-4.197 2.6,-3.803
3D body: height 0.36, standoff -0.04, extent -1.799,-4.197 -1.4,-3.803
3D body: height 0.36, standoff -0.04, extent -0.999,-4.197 -0.6,-3.803
3D body: height 0.36, standoff -0.04, extent -0.199,-4.197 0.2,-3.803
3D body: height 0.36, standoff -0.04, extent 0.601,-4.197 1,-3.803
3D body: height 0.36, standoff -0.04, extent 1.401,-4.197 1.8,-3.803
3D body: height 0.36, standoff -0.04, extent -5.799,-4.197 -5.4,-3.803
3D body: height 0.36, standoff -0.04, extent -4.999,-4.197 -4.6,-3.803
3D body: height 0.36, standoff -0.04, extent -4.199,-4.197 -3.8,-3.803
3D body: height 0.36, standoff -0.04, extent -3.399,-4.197 -3,-3.803
3D body: height 0.36, standoff -0.04, extent -2.599,-4.197 -2.2,-3.803
3D body: height 0.36, standoff -0.04, extent 5.401,-3.397 5.8,-3.003
3D body: height 0.36, standoff -0.04, extent 4.601,-3.397 5,-3.003
3D body: height 0.36, standoff -0.04, extent 3.801,-3.397 4.2,-3.003
3D body: height 0.36, standoff -0.04, extent 3.001,-3.397 3.4,-3.003
3D body: height 0.36, standoff -0.04, extent 2.201,-3.397 2.6,-3.003
3D body: height 0.36, standoff -0.04, extent -1.799,-3.397 -1.4,-3.003
3D body: height 0.36, standoff -0.04, extent -0.999,-3.397 -0.6,-3.003
3D body: height 0.36, standoff -0.04, extent -0.199,-3.397 0.2,-3.003
3D body: height 0.36, standoff -0.04, extent 0.601,-3.397 1,-3.003
3D body: height 0.36, standoff -0.04, extent 1.401,-3.397 1.8,-3.003
3D body: height 0.36, standoff -0.04, extent -5.799,-3.397 -5.4,-3.003
3D body: height 0.36, standoff -0.04, extent -4.999,-3.397 -4.6,-3.003
3D body: height 0.36, standoff -0.04, extent -4.199,-3.397 -3.8,-3.003
3D body: height 0.36, standoff -0.04, extent -3.399,-3.397 -3,-3.003
3D body: height 0.36, standoff -0.04, extent -2.599,-3.397 -2.2,-3.003
3D body: height 0.36, standoff -0.04, extent 5.401,-2.597 5.8,-2.203
3D body: height 0.36, standoff -0.04, extent 4.601,-2.597 5,-2.203
3D body: height 0.36, standoff -0.04, extent 3.801,-2.597 4.2,-2.203
3D body: height 0.36, standoff -0.04, extent 3.001,-2.597 3.4,-2.203
3D body: height 0.36, standoff -0.04, extent 2.201,-2.597 2.6,-2.203
3D body: height 0.36, standoff -0.04, extent -1.799,-2.597 -1.4,-2.203
3D body: height 0.36, standoff -0.04, extent -0.999,-2.597 -0.6,-2.203
3D body: height 0.36, standoff -0.04, extent -0.199,-2.597 0.2,-2.203
3D body: height 0.36, standoff -0.04, extent 0.601,-2.597 1,-2.203
3D body: height 0.36, standoff -0.04, extent 1.401,-2.597 1.8,-2.203
3D body: height 0.36, standoff -0.04, extent -5.799,-2.597 -5.4,-2.203
3D body: height 0.36, standoff -0.04, extent -4.999,-2.597 -4.6,-2.203
3D body: height 0.36, standoff -0.04, extent -4.199,-2.597 -3.8,-2.203
3D body: height 0.36, standoff -0.04, extent -3.399,-2.597 -3,-2.203
3D body: height 0.36, standoff -0.04, extent -2.599,-2.597 -2.2,-2.203
3D body: height 0.36, standoff -0.04, extent 5.401,-1.797 5.8,-1.403
3D body: height 0.36, standoff -0.04, extent 4.601,-1.797 5,-1.403
3D body: height 0.36, standoff -0.04, extent 3.801,-1.797 4.2,-1.403
3D body: height 0.36, standoff -0.04, extent 3.001,-1.797 3.4,-1.403
3D body: height 0.36, standoff -0.04, extent 2.201,-1.797 2.6,-1.403
3D body: height 0.36, standoff -0.04, extent -1.799,-1.797 -1.4,-1.403
3D body: height 0.36, standoff -0.04, extent -0.999,-1.797 -0.6,-1.403
3D body: height 0.36, standoff -0.04, extent -0.199,-1.797 0.2,-1.403
3D body: height 0.36, standoff -0.04, extent 0.601,-1.797 1,-1.403
3D body: height 0.36, standoff -0.04, extent 1.401,-1.797 1.8,-1.403
3D body: height 0.36, standoff -0.04, extent -5.799,-1.797 -5.4,-1.403
3D body: height 0.36, standoff -0.04, extent -4.999,-1.797 -4.6,-1.403
3D body: height 0.36, standoff -0.04, extent -4.199,-1.797 -3.8,-1.403
3D body: height 0.36, standoff -0.04, extent -3.399,-1.797 -3,-1.403
3D body: height 0.36, standoff -0.04, extent -2.599,-1.797 -2.2,-1.403
3D body: height 0.36, standoff -0.04, extent 5.401,-0.997 5.8,-0.603
3D body: height 0.36, standoff -0.04, extent 4.601,-0.997 5,-0.603
3D body: height 0.36, standoff -0.04, extent 3.801,-0.997 4.2,-0.603
3D body: height 0.36, standoff -0.04, extent 3.001,-0.997 3.4,-0.603
3D body: height 0.36, standoff -0.04, extent 2.201,-0.997 2.6,-0.603
3D body: height 0.36, standoff -0.04, extent -1.799,-0.997 -1.4,-0.603
3D body: height 0.36, standoff -0.04, extent -0.999,-0.997 -0.6,-0.603
3D body: height 0.36, standoff -0.04, extent -0.199,-0.997 0.2,-0.603
3D body: height 0.36, standoff -0.04, extent 0.601,-0.997 1,-0.603
3D body: height 0.36, standoff -0.04, extent 1.401,-0.997 1.8,-0.603
3D body: height 0.36, standoff -0.04, extent -5.799,-0.997 -5.4,-0.603
3D body: height 0.36, standoff -0.04, extent -4.999,-0.997 -4.6,-0.603
3D body: height 0.36, standoff -0.04, extent -4.199,-0.997 -3.8,-0.603
3D body: height 0.36, standoff -0.04, extent -3.399,-0.997 -3,-0.603
3D body: height 0.36, standoff -0.04, extent -2.599,-0.997 -2.2,-0.603
3D body: height 0.36, standoff -0.04, extent 5.401,-0.197 5.8,0.197
3D body: height 0.36, standoff -0.04, extent 4.601,-0.197 5,0.197
3D body: height 0.36, standoff -0.04, extent 3.801,-0.197 4.2,0.197
3D body: height 0.36, standoff -0.04, extent 3.001,-0.197 3.4,0.197
3D body: height 0.36, standoff -0.04, extent 2.201,-0.197 2.6,0.197
3D body: height 0.36, standoff -0.04, extent -1.799,-0.197 -1.4,0.197
3D body: height 0.36, standoff -0.04, extent -0.999,-0.197 -0.6,0.197
3D body: height 0.36, standoff -0.04, extent -0.199,-0.197 0.2,0.197
3D body: height 0.36, standoff -0.04, extent 0.601,-0.197 1,0.197
3D body: height 0.36, standoff -0.04, extent 1.401,-0.197 1.8,0.197
3D body: height 0.36, standoff -0.04, extent -5.799,-0.197 -5.4,0.197
3D body: height 0.36, standoff -0.04, extent -4.999,-0.197 -4.6,0.197
3D body: height 0.36, standoff -0.04, extent -4.199,-0.197 -3.8,0.197
3D body: height 0.36, standoff -0.04, extent -3.399,-0.197 -3,0.197
3D body: height 0.36, standoff -0.04, extent -2.599,-0.197 -2.2,0.197
3D body: height 0.36, standoff -0.04, extent 5.401,0.603 5.8,0.997
3D body: height 0.36, standoff -0.04, extent 4.601,0.603 5,0.997
3D body: height 0.36, standoff -0.04, extent 3.801,0.603 4.2,0.997
3D body: height 0.36, standoff -0.04, extent 3.001,0.603 3.4,0.997
3D body: height 0.36, standoff -0.04, extent 2.201,0.603 2.6,0.997
3D body: height 0.36, standoff -0.04, extent -1.799,0.603 -1.4,0.997
3D body: height 0.36, standoff -0.04, extent -0.999,0.603 -0.6,0.997
3D body: height 0.36, standoff -0.04, extent -0.199,0.603 0.2,0.997
3D body: height 0.36, standoff -0.04, extent 0.601,0.603 1,0.997
3D body: height 0.36, standoff -0.04, extent 1.401,0.603 1.8,0.997
3D body: height 0.36, standoff -0.04, extent -5.799,0.603 -5.4,0.997
3D body: height 0.36, standoff -0.04, extent -4.999,0.603 -4.6,0.997
3D body: height 0.36, standoff -0.04, extent -4.199,0.603 -3.8,0.997
3D body: height 0.36, standoff -0.04, extent -3.399,0.603 -3,0.997
3D body: height 0.36, standoff -0.04, extent -2.599,0.603 -2.2,0.997
3D body: height 0.36, standoff -0.04, extent 5.401,1.403 5.8,1.797
3D body: height 0.36, standoff -0.04, extent 4.601,1.403 5,1.797
3D body: height 0.36, standoff -0.04, extent 3.801,1.403 4.2,1.797
3D body: height 0.36, standoff -0.04, extent 3.001,1.403 3.4,1.797
3D body: height 0.36, standoff -0.04, extent 2.201,1.403 2.6,1.797
3D body: height 0.36, standoff -0.04, extent -1.799,1.403 -1.4,1.797
3D body: height 0.36, standoff -0.04, extent -0.999,1.403 -0.6,1.797
3D body: height 0.36, standoff -0.04, extent -0.199,1.403 0.2,1.797
3D body: height 0.36, standoff -0.04, extent 0.601,1.403 1,1.797
3D body: height 0.36, standoff -0.04, extent 1.401,1.403 1.8,1.797
3D body: height 0.36, standoff -0.04, extent -5.799,1.403 -5.4,1.797
3D body: height 0.36, standoff -0.04, extent -4.999,1.403 -4.6,1.797
3D body: height 0.36, standoff -0.04, extent -4.199,1.403 -3.8,1.797
3D body: height 0.36, standoff -0.04, extent -3.399,1.403 -3,1.797
3D body: height 0.36, standoff -0.04, extent -2.599,1.403 -2.2,1.797
3D body: height 0.36, standoff -0.04, extent 5.401,2.203 5.8,2.597
3D body: height 0.36, standoff -0.04, extent 4.601,2.203 5,2.597
3D body: height 0.36, standoff -0.04, extent 3.801,2.203 4.2,2.597
3D body: height 0.36, standoff -0.04, extent 3.001,2.203 3.4,2.597
3D body: height 0.36, standoff -0.04, extent 2.201,2.203 2.6,2.597
3D body: height 0.36, standoff -0.04, extent -1.799,2.203 -1.4,2.597
3D body: height 0.36, standoff -0.04, extent -0.999,2.203 -0.6,2.597
3D body: height 0.36, standoff -0.04, extent -0.199,2.203 0.2,2.597
3D body: height 0.36, standoff -0.04, extent 0.601,2.203 1,2.597
3D body: height 0.36, standoff -0.04, extent 1.401,2.203 1.8,2.597
3D body: height 0.36, standoff -0.04, extent -5.799,2.203 -5.4,2.597
3D body: height 0.36, standoff -0.04, extent -4.999,2.203 -4.6,2.597
3D body: height 0.36, standoff -0.04, extent -4.199,2.203 -3.8,2.597
3D body: height 0.36, standoff -0.04, extent -3.399,2.203 -3,2.597
3D body: height 0.36, standoff -0.04, extent -2.599,2.203 -2.2,2.597
3D body: height 0.36, standoff -0.04, extent 5.401,3.003 5.8,3.397
3D body: height 0.36, standoff -0.04, extent 4.601,3.003 5,3.397
3D body: height 0.36, standoff -0.04, extent 3.801,3.003 4.2,3.397
3D body: height 0.36, standoff -0.04, extent 3.001,3.003 3.4,3.397
3D body: height 0.36, standoff -0.04, extent 2.201,3.003 2.6,3.397
3D body: height 0.36, standoff -0.04, extent -1.799,3.003 -1.4,3.397
3D body: height 0.36, standoff -0.04, extent -0.999,3.003 -0.6,3.397
3D body: height 0.36, standoff -0.04, extent -0.199,3.003 0.2,3.397
3D body: height 0.36, standoff -0.04, extent 0.601,3.003 1,3.397
3D body: height 0.36, standoff -0.04, extent 1.401,3.003 1.8,3.397
3D body: height 0.36, standoff -0.04, extent -5.799,3.003 -5.4,3.397
3D body: height 0.36, standoff -0.04, extent -4.999,3.003 -4.6,3.397
3D body: height 0.36, standoff -0.04, extent -4.199,3.003 -3.8,3.397
3D body: height 0.36, standoff -0.04, extent -3.399,3.003 -3,3.397
3D body: height 0.36, standoff -0.04, extent -2.599,3.003 -2.2,3.397
3D body: height 0.36, standoff -0.04, extent 5.401,3.803 5.8,4.197
3D body: height 0.36, standoff -0.04, extent 4.601,3.803 5,4.197
3D body: height 0.36, standoff -0.04, extent 3.801,3.803 4.2,4.197
3D body: height 0.36, standoff -0.04, extent 3.001,3.803 3.4,4.197
3D body: height 0.36, standoff -0.04, extent 2.201,3.803 2.6,4.197
3D body: height 0.36, standoff -0.04, extent -1.799,3.803 -1.4,4.197
3D body: height 0.36, standoff -0.04, extent -0.999,3.803 -0.6,4.197
3D body: height 0.36, standoff -0.04, extent -0.199,3.803 0.2,4.197
3D body: height 0.36, standoff -0.04, extent 0.601,3.803 1,4.197
3D body: height 0.36, standoff -0.04, extent 1.401,3.803 1.8,4.197
3D body: height 0.36, standoff -0.04, extent -5.799,3.803 -5.4,4.197
3D body: height 0.36, standoff -0.04, extent -4.999,3.803 -4.6,4.197
3D body: height 0.36, standoff -0.04, extent -4.199,3.803 -3.8,4.197
3D body: height 0.36, standoff -0.04, extent -3.399,3.803 -3,4.197
3D body: height 0.36, standoff -0.04, extent -2.599,3.803 -2.2,4.197
3D body: height 0.36, standoff -0.04, extent 5.401,4.603 5.8,4.997
3D body: height 0.36, standoff -0.04, extent 4.601,4.603 5,4.997
3D body: height 0.36, standoff -0.04, extent 3.801,4.603 4.2,4.997
3D body: height 0.36, standoff -0.04, extent 3.001,4.603 3.4,4.997
3D body: height 0.36, standoff -0.04, extent 2.201,4.603 2.6,4.997
3D body: height 0.36, standoff -0.04, extent -1.799,4.603 -1.4,4.997
3D body: height 0.36, standoff -0.04, extent -0.999,4.603 -0.6,4.997
3D body: height 0.36, standoff -0.04, extent -0.199,4.603 0.2,4.997
3D body: height 0.36, standoff -0.04, extent 0.601,4.603 1,4.997
3D body: height 0.36, standoff -0.04, extent 1.401,4.603 1.8,4.997
3D body: height 0.36, standoff -0.04, extent -5.799,4.603 -5.4,4.997
3D body: height 0.36, standoff -0.04, extent -4.999,4.603 -4.6,4.997
3D body: height 0.36, standoff -0.04, extent -4.199,4.603 -3.8,4.997
3D body: height 0.36, standoff -0.04, extent -3.399,4.603 -3,4.997
3D body: height 0.36, standoff -0.04, extent -2.599,4.603 -2.2,4.997
3D body: height 0.36, standoff -0.04, extent -2.599,5.403 -2.2,5.797
3D body: height 0.36, standoff -0.04, extent -3.399,5.403 -3,5.797
3D body: height 0.36, standoff -0.04, extent -4.199,5.403 -3.8,5.797
3D body: height 0.36, standoff -0.04, extent -4.999,5.403 -4.6,5.797
3D body: height 0.36, standoff -0.04, extent -5.799,5.403 -5.4,5.797
3D body: height 0.36, standoff -0.04, extent 1.401,5.403 1.8,5.797
3D body: height 0.36, standoff -0.04, extent 0.601,5.403 1,5.797
3D body: height 0.36, standoff -0.04, extent -0.199,5.403 0.2,5.797
3D body: height 0.36, standoff -0.04, extent -0.999,5.403 -0.6,5.797
3D body: height 0.36, standoff -0.04, extent -1.799,5.403 -1.4,5.797
3D body: height 0.36, standoff -0.04, extent 2.201,5.403 2.6,5.797
3D body: height 0.36, standoff -0.04, extent 3.001,5.403 3.4,5.797
3D body: height 0.36, standoff -0.04, extent 3.801,5.403 4.2,5.797
3D body: height 0.36, standoff -0.04, extent 4.601,5.403 5,5.797
3D body: height 1.2, standoff 0.3, extent -6.55,-6.55 6.55,6.55
3D body: height 0.36, standoff -0.04, extent 5.401,5.403 5.8,5.797
3D body: height 8.26, standoff 8.25, extent -1.375,-1 0.625,1
3D body: height 5, standoff 0, extent -9.488,-9.113 8.737,9.112
3D body: height 8.25, standoff 5, extent -3.375,-3 2.625,3
3D body: height 6, standoff 5, extent -1.218,-8.711 0.475,-7.014
3D body: height 6, standoff 5, extent 6.644,-0.848 8.338,0.848
3D body: height 6, standoff 5, extent -1.218,7.014 0.475,8.711
3D body: height 6, standoff 5, extent -9.081,-0.848 -7.387,0.848
3D body: height -1.6, standoff -3.2, extent -10.74,-10.365 9.99,10.365
3D body: height -3.2, standoff -9.55, extent -10.74,-10.365 9.99,10.365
